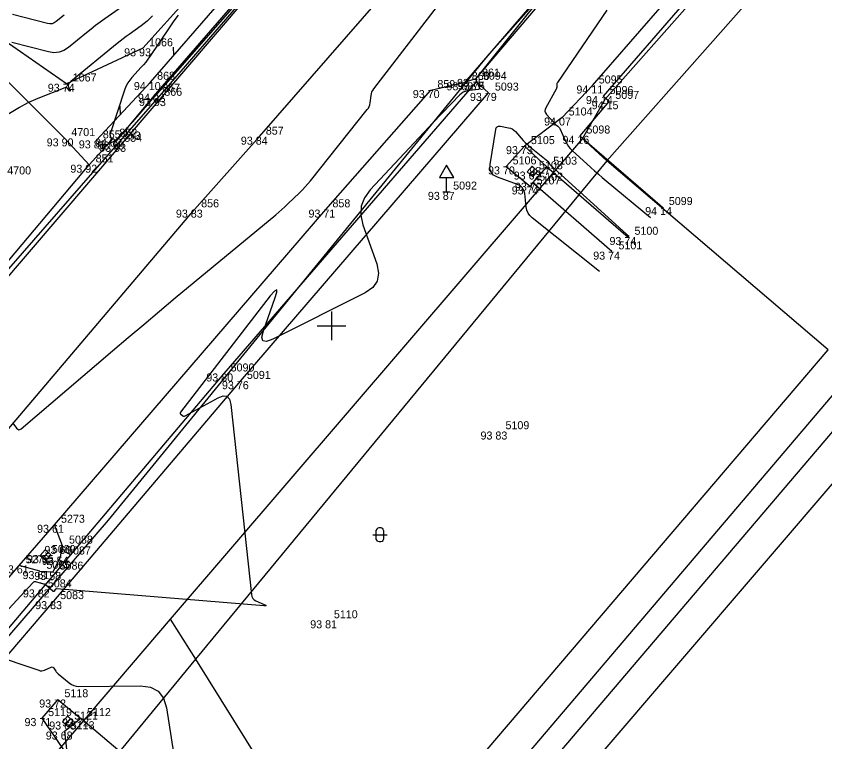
# Model space of a CAD drawing. Extents: x -711081 to -709338, y -1025122 to -1024092.
# Drawn here: x -709736.03 to -709707.76, y -1024464.55 to -1024439.18 of the extents above; entities that cross this region are included whole.
import ezdxf

# ---------------------------------------------------------------- set-up
doc = ezdxf.new("R2010")
doc.units = 0
for name, color, linetype in [('Ex_Major Contours', 7, 'Continuous'), ('Ex_Minor Contours', 7, 'Continuous'), ('Z_body', 7, 'Continuous'), ('Z_body_cisla', 7, 'Continuous'), ('Z_body_vysky_redukovane', 7, 'Continuous'), ('Z_dopravni_znacky', 7, 'Continuous'), ('Z_hektometricka_sit', 7, 'Continuous'), ('Z_hrany_paty', 7, 'Continuous'), ('Z_katastr_hranice', 7, 'Continuous'), ('Z_katastr_vnitrni_kresba', 7, 'Continuous'), ('Z_komunikace', 7, 'Continuous'), ('Z_obruba', 7, 'Continuous'), ('Z_rozhranni', 7, 'Continuous'), ('Z_site_kanalizace_znaky', 7, 'Continuous'), ('Z_svodidla', 7, 'Continuous'), ('Z_svodidla_znacky', 7, 'Continuous'), ('Z_svodidlo_betonove', 7, 'Continuous'), ('Z_vdz12_plna', 7, 'Continuous'), ('Z_vdz12_prerusovana', 7, 'Continuous'), ('Z_zlabek', 7, 'Continuous'), ('Z_znaky_kultur', 7, 'Continuous')]:
    doc.layers.add(name, color=color, linetype=linetype)

# ---------------------------------------------------------------- blocks, each defined once
blk = doc.blocks.new('POINT_DISPLAY')
blk.add_line((0, 0), (0, 0))
blk = doc.blocks.new('Z529')
blk.add_line((0, 0), (0.2, 0.2))
blk = doc.blocks.new('Z46260')
for p, q in [((0.13, 0.13), (-0.13, 0.13)), ((-0.13, 0.13), (-0.13, -0.13)), ((0.13, 0), (-0.13, 0)), ((0.13, -0.13), (0.13, 0.13)), ((-0.13, -0.13), (0.13, -0.13))]:
    blk.add_line(p, q)
blk = doc.blocks.new('Z527')
for p, q in [((0, 0.93), (-0.25, 0.5)), ((0.25, 0.5), (0, 0.93)), ((-0.25, 0.5), (0.25, 0.5)), ((0, 0), (0, 0.5)), ((-0.13, 0), (0.13, 0))]:
    blk.add_line(p, q)
blk = doc.blocks.new('Z316')
for p, q in [((-0.25, 0), (0.25, 0)), ((-0.13, 0.15), (-0.1, 0.2)), ((-0.13, -0.15), (-0.13, 0.15)), ((-0.1, 0.2), (-0.08, 0.23)), ((-0.08, 0.23), (-0.03, 0.25)), ((-0.03, 0.25), (0.03, 0.25)), ((0.03, 0.25), (0.08, 0.23)), ((0.08, 0.23), (0.1, 0.2)), ((0.1, 0.2), (0.13, 0.15)), ((0.13, 0.15), (0.13, -0.15)), ((-0.1, -0.2), (-0.13, -0.15)), ((-0.08, -0.23), (-0.1, -0.2)), ((-0.03, -0.25), (-0.08, -0.23)), ((0.03, -0.25), (-0.03, -0.25)), ((0.08, -0.23), (0.03, -0.25)), ((0.1, -0.2), (0.08, -0.23)), ((0.13, -0.15), (0.1, -0.2))]:
    blk.add_line(p, q)

msp = doc.modelspace()

# ---------------------------------------------------------------- linework, layer by layer
at = {"layer": 'Ex_Major Contours'}
for points in [[(-709730.362, -1024439.145), (-709730.511, -1024439.344), (-709730.653, -1024439.548), (-709731.353, -1024440.585), (-709731.423, -1024440.684), (-709731.496, -1024440.78), (-709731.573, -1024440.873), (-709731.653, -1024440.964), (-709731.982, -1024441.319), (-709732.059, -1024441.411), (-709732.125, -1024441.51), (-709732.18, -1024441.615), (-709732.223, -1024441.726), (-709732.744, -1024443.286), (-709732.749, -1024443.304), (-709732.75, -1024443.323), (-709732.747, -1024443.341), (-709732.741, -1024443.359), (-709732.711, -1024443.43), (-709732.706, -1024443.448), (-709732.705, -1024443.465), (-709732.709, -1024443.482), (-709732.717, -1024443.498), (-709732.78, -1024443.598), (-709732.789, -1024443.616), (-709732.789, -1024443.625), (-709732.78, -1024443.627), (-709732.761, -1024443.619), (-709732.627, -1024443.556), (-709732.598, -1024443.54), (-709732.57, -1024443.522), (-709732.544, -1024443.501), (-709732.52, -1024443.478), (-709732.192, -1024443.134), (-709732.13, -1024443.068), (-709732.068, -1024443.002), (-709732.008, -1024442.935), (-709731.948, -1024442.867), (-709731.362, -1024442.193), (-709731.244, -1024442.058), (-709731.126, -1024441.924), (-709731.009, -1024441.789), (-709730.891, -1024441.654), (-709726.88, -1024437.076)], [(-709715.38, -1024438.972), (-709717.104, -1024441.497), (-709717.114, -1024441.514), (-709717.121, -1024441.531), (-709717.125, -1024441.55), (-709717.127, -1024441.57), (-709717.128, -1024441.649), (-709717.129, -1024441.669), (-709717.133, -1024441.688), (-709717.139, -1024441.706), (-709717.147, -1024441.724), (-709717.514, -1024442.382), (-709717.538, -1024442.443), (-709717.542, -1024442.501), (-709717.526, -1024442.557), (-709717.489, -1024442.61), (-709717.245, -1024442.887), (-709717.227, -1024442.906), (-709717.208, -1024442.924), (-709717.189, -1024442.942), (-709717.169, -1024442.959), (-709717.086, -1024443.024), (-709717.067, -1024443.041), (-709717.05, -1024443.06), (-709717.035, -1024443.081), (-709717.023, -1024443.104), (-709716.811, -1024443.575), (-709716.768, -1024443.658), (-709716.717, -1024443.736), (-709716.658, -1024443.809), (-709716.592, -1024443.875), (-709715.94, -1024444.468), (-709715.808, -1024444.588), (-709715.673, -1024444.705), (-709715.538, -1024444.821), (-709715.401, -1024444.936), (-709713.85, -1024446.218)]]:
    msp.add_lwpolyline(points, dxfattribs=at)
at = {"layer": 'Ex_Minor Contours'}
for points in [[(-709731.728, -1024438.421), (-709732.924, -1024439.265), (-709733.089, -1024439.384), (-709733.251, -1024439.505), (-709733.411, -1024439.63), (-709733.569, -1024439.757), (-709734.196, -1024440.273), (-709734.358, -1024440.379), (-709734.53, -1024440.441), (-709734.711, -1024440.457), (-709734.903, -1024440.428), (-709736.179, -1024440.095)], [(-709717.931, -1024438.822), (-709718.222, -1024439.185), (-709719.944, -1024441.35), (-709719.95, -1024441.36), (-709719.954, -1024441.371), (-709719.955, -1024441.383), (-709719.953, -1024441.395), (-709719.938, -1024441.445), (-709719.934, -1024441.457), (-709719.929, -1024441.47), (-709719.924, -1024441.482), (-709719.919, -1024441.494), (-709719.839, -1024441.662), (-709719.83, -1024441.69), (-709719.833, -1024441.712), (-709719.849, -1024441.727), (-709719.878, -1024441.736), (-709720.258, -1024441.793), (-709720.33, -1024441.81), (-709720.397, -1024441.837), (-709720.458, -1024441.875), (-709720.513, -1024441.924), (-709721.128, -1024442.559), (-709721.248, -1024442.683), (-709721.367, -1024442.808), (-709721.486, -1024442.934), (-709721.604, -1024443.059), (-709723.649, -1024445.254), (-709723.851, -1024445.529), (-709723.961, -1024445.823), (-709723.978, -1024446.137), (-709723.904, -1024446.47), (-709723.421, -1024447.841), (-709723.356, -1024448.162), (-709723.403, -1024448.437), (-709723.56, -1024448.667), (-709723.829, -1024448.853), (-709727.049, -1024450.471), (-709727.271, -1024450.554), (-709727.4, -1024450.532), (-709727.437, -1024450.406), (-709727.382, -1024450.177), (-709726.979, -1024449.05), (-709726.914, -1024448.833), (-709726.92, -1024448.746), (-709726.996, -1024448.788), (-709727.144, -1024448.96), (-709730.284, -1024453.025), (-709730.295, -1024453.043), (-709730.297, -1024453.06), (-709730.291, -1024453.076), (-709730.276, -1024453.091), (-709730.202, -1024453.149), (-709730.183, -1024453.16), (-709730.164, -1024453.165), (-709730.144, -1024453.163), (-709730.124, -1024453.155), (-709728.968, -1024452.519), (-709728.791, -1024452.452), (-709728.657, -1024452.468), (-709728.567, -1024452.568), (-709728.521, -1024452.753), (-709727.805, -1024459.402), (-709727.789, -1024459.474), (-709727.757, -1024459.534), (-709727.709, -1024459.583), (-709727.645, -1024459.62), (-709727.359, -1024459.744), (-709727.306, -1024459.771), (-709727.29, -1024459.788), (-709727.312, -1024459.796), (-709727.371, -1024459.794), (-709734.615, -1024459.205), (-709734.63, -1024459.205), (-709734.643, -1024459.209), (-709734.655, -1024459.217), (-709734.665, -1024459.228), (-709734.701, -1024459.278), (-709734.711, -1024459.288), (-709734.721, -1024459.292), (-709734.732, -1024459.291), (-709734.743, -1024459.283), (-709734.997, -1024459.065), (-709735.01, -1024459.054), (-709735.025, -1024459.046), (-709735.041, -1024459.039), (-709735.057, -1024459.033), (-709735.126, -1024459.016), (-709735.143, -1024459.011), (-709735.16, -1024459.007), (-709735.177, -1024459.002), (-709735.194, -1024458.997), (-709735.34, -1024458.957), (-709735.369, -1024458.952), (-709735.396, -1024458.956), (-709735.42, -1024458.967), (-709735.442, -1024458.986), (-709737.12, -1024460.795)], [(-709736.15, -1024453.402), (-709736.011, -1024453.587), (-709735.975, -1024453.622), (-709735.937, -1024453.637), (-709735.896, -1024453.631), (-709735.853, -1024453.604), (-709732.664, -1024450.88), (-709732.117, -1024450.415), (-709731.568, -1024449.952), (-709731.018, -1024449.49), (-709730.465, -1024449.031), (-709726.948, -1024446.12), (-709726.84, -1024446.029), (-709726.734, -1024445.936), (-709726.629, -1024445.841), (-709726.526, -1024445.744), (-709726.118, -1024445.352), (-709726.018, -1024445.252), (-709725.921, -1024445.149), (-709725.827, -1024445.043), (-709725.737, -1024444.934), (-709723.751, -1024442.445), (-709723.714, -1024442.392), (-709723.686, -1024442.335), (-709723.666, -1024442.275), (-709723.653, -1024442.212), (-709723.622, -1024441.951), (-709723.61, -1024441.888), (-709723.59, -1024441.827), (-709723.562, -1024441.771), (-709723.526, -1024441.717), (-709721.294, -1024438.828)], [(-709731.267, -1024439.168), (-709731.356, -1024439.263), (-709731.451, -1024439.352), (-709731.55, -1024439.435), (-709731.654, -1024439.513), (-709732.08, -1024439.814), (-709732.186, -1024439.891), (-709732.29, -1024439.969), (-709732.393, -1024440.049), (-709732.495, -1024440.131), (-709734.113, -1024441.461), (-709734.121, -1024441.468), (-709734.129, -1024441.475), (-709734.137, -1024441.483), (-709734.144, -1024441.491), (-709734.176, -1024441.525), (-709734.182, -1024441.532), (-709734.187, -1024441.539), (-709734.191, -1024441.547), (-709734.194, -1024441.556), (-709734.206, -1024441.591), (-709734.208, -1024441.6), (-709734.209, -1024441.608), (-709734.207, -1024441.617), (-709734.205, -1024441.626), (-709734.143, -1024441.771), (-709734.136, -1024441.791), (-709734.136, -1024441.8), (-709734.144, -1024441.797), (-709734.16, -1024441.782), (-709734.236, -1024441.7), (-709734.256, -1024441.684), (-709734.277, -1024441.675), (-709734.301, -1024441.673), (-709734.326, -1024441.68), (-709735.27, -1024442.051), (-709735.434, -1024442.12), (-709735.595, -1024442.195), (-709735.753, -1024442.277), (-709735.907, -1024442.366), (-709736.677, -1024442.828)], [(-709734.354, -1024439.145), (-709734.625, -1024439.368), (-709734.694, -1024439.414), (-709734.769, -1024439.44), (-709734.847, -1024439.447), (-709734.93, -1024439.435), (-709736.156, -1024439.115)], [(-709715.638, -1024448.109), (-709717.987, -1024446.23), (-709718.069, -1024446.15), (-709718.132, -1024446.06), (-709718.174, -1024445.96), (-709718.197, -1024445.848), (-709718.249, -1024445.379), (-709718.275, -1024445.271), (-709718.324, -1024445.183), (-709718.398, -1024445.114), (-709718.497, -1024445.064), (-709719.203, -1024444.805), (-709719.335, -1024444.735), (-709719.421, -1024444.639), (-709719.463, -1024444.516), (-709719.459, -1024444.367), (-709719.262, -1024443.145), (-709719.243, -1024443.084), (-709719.209, -1024443.044), (-709719.16, -1024443.025), (-709719.097, -1024443.027), (-709718.812, -1024443.076), (-709718.744, -1024443.093), (-709718.682, -1024443.121), (-709718.625, -1024443.159), (-709718.574, -1024443.208), (-709718.297, -1024443.521), (-709718.234, -1024443.59), (-709718.167, -1024443.655), (-709718.098, -1024443.718), (-709718.026, -1024443.778), (-709717.441, -1024444.242), (-709717.431, -1024444.25), (-709717.422, -1024444.26), (-709717.415, -1024444.27), (-709717.409, -1024444.282), (-709717.388, -1024444.329), (-709717.382, -1024444.341), (-709717.375, -1024444.352), (-709717.367, -1024444.362), (-709717.358, -1024444.371), (-709714.687, -1024446.8), (-709714.679, -1024446.808), (-709714.67, -1024446.816), (-709714.661, -1024446.823), (-709714.653, -1024446.83), (-709714.6, -1024446.874)], [(-709736.95, -1024461.468), (-709735.235, -1024462.049), (-709735.184, -1024462.062), (-709735.134, -1024462.065), (-709735.085, -1024462.058), (-709735.035, -1024462.041), (-709734.799, -1024461.94), (-709734.772, -1024461.932), (-709734.747, -1024461.935), (-709734.726, -1024461.947), (-709734.708, -1024461.969), (-709734.641, -1024462.078), (-709734.624, -1024462.104), (-709734.604, -1024462.128), (-709734.583, -1024462.151), (-709734.559, -1024462.172), (-709734.172, -1024462.492), (-709734.096, -1024462.544), (-709734.016, -1024462.581), (-709733.929, -1024462.603), (-709733.838, -1024462.61), (-709731.677, -1024462.593), (-709731.326, -1024462.639), (-709731.059, -1024462.782), (-709730.874, -1024463.022), (-709730.772, -1024463.361), (-709730.279, -1024466.513)]]:
    msp.add_lwpolyline(points, dxfattribs=at)
at = {"layer": 'Z_hektometricka_sit'}
for p, q in [((-709725, -1024449.5), (-709725, -1024450.5)), ((-709725.5, -1024450), (-709724.5, -1024450))]:
    msp.add_line(p, q, dxfattribs=at)
at = {"layer": 'Z_hrany_paty'}
for p, q in [((-709726.88, -1024435.04), (-709731.6, -1024440.3)), ((-709734.27, -1024441.54), (-709737.37, -1024439.39)), ((-709731.6, -1024440.3), (-709734.27, -1024441.54))]:
    msp.add_line(p, q, dxfattribs=at)
at = {"layer": 'Z_katastr_hranice'}
for p, q in [((-709705.62, -1024430.99), (-709715.45, -1024442.09)), ((-709715.45, -1024442.09), (-709716.23, -1024443.45)), ((-709716.23, -1024443.45), (-709730.64, -1024460.26)), ((-709715.38, -1024444.24), (-709716.23, -1024443.45)), ((-709707.64, -1024450.84), (-709715.38, -1024444.24)), ((-709730.64, -1024460.26), (-709735.48, -1024465.91)), ((-709730.64, -1024460.26), (-709729.76, -1024461.66)), ((-709729.76, -1024461.66), (-709724.31, -1024470.38))]:
    msp.add_line(p, q, dxfattribs=at)
at = {"layer": 'Z_katastr_vnitrni_kresba'}
for p, q in [((-709719.49, -1024440.51), (-709707.87, -1024427.32)), ((-709715.38, -1024444.24), (-709704.82, -1024432.3)), ((-709725.38, -1024435.5), (-709769.86, -1024487.47)), ((-709732.8, -1024456.8), (-709719.49, -1024440.51)), ((-709715.38, -1024444.24), (-709729.76, -1024461.66)), ((-709724.31, -1024470.38), (-709707.64, -1024450.84)), ((-709723.64, -1024471.44), (-709706.77, -1024451.59)), ((-709706.15, -1024452.12), (-709723.19, -1024472.15)), ((-709705.25, -1024452.89), (-709722.57, -1024473.13)), ((-709754.46, -1024481.94), (-709732.8, -1024456.8)), ((-709729.76, -1024461.66), (-709734.52, -1024467.43))]:
    msp.add_line(p, q, dxfattribs=at)
at = {"layer": 'Z_komunikace'}
for p, q in [((-709731.08, -1024442.04), (-709719.72, -1024428.91)), ((-709720.33, -1024441.49), (-709713.34, -1024433.37)), ((-709710.24, -1024435.89), (-709715.5, -1024441.97)), ((-709734.33, -1024443.45), (-709737.89, -1024439.9)), ((-709721.53, -1024441.76), (-709720.33, -1024441.49)), ((-709725.2, -1024445.94), (-709721.53, -1024441.76)), ((-709715.5, -1024441.97), (-709715.3, -1024442.15)), ((-709732.47, -1024443.64), (-709731.08, -1024442.04)), ((-709715.3, -1024442.15), (-709716.32, -1024443.36)), ((-709716.32, -1024443.36), (-709713.43, -1024445.85)), ((-709737.55, -1024449.46), (-709732.47, -1024443.64)), ((-709734.33, -1024443.45), (-709733.48, -1024444.37)), ((-709734.69, -1024456.96), (-709725.2, -1024445.94)), ((-709735.92, -1024458.38), (-709734.69, -1024456.96)), ((-709734.41, -1024457.7), (-709734.69, -1024456.96)), ((-709734.48, -1024458.08), (-709734.41, -1024457.7)), ((-709734.74, -1024458.61), (-709734.48, -1024458.08)), ((-709740.66, -1024463.89), (-709735.92, -1024458.38)), ((-709735.2, -1024458.58), (-709735.92, -1024458.38)), ((-709735.2, -1024458.58), (-709734.74, -1024458.61))]:
    msp.add_line(p, q, dxfattribs=at)
at = {"layer": 'Z_obruba'}
for p, q in [((-709731.14, -1024441.89), (-709719.85, -1024428.88)), ((-709719.96, -1024441.37), (-709713.42, -1024433.69)), ((-709719.96, -1024441.37), (-709720.33, -1024441.49)), ((-709732.53, -1024443.56), (-709731.14, -1024441.89)), ((-709733.48, -1024444.37), (-709732.64, -1024443.46)), ((-709732.64, -1024443.46), (-709732.53, -1024443.56)), ((-709737.58, -1024449.25), (-709733.48, -1024444.37))]:
    msp.add_line(p, q, dxfattribs=at)
at = {"layer": 'Z_rozhranni'}
for p, q in [((-709715.88, -1024441.6), (-709710.61, -1024435.54)), ((-709715.88, -1024441.6), (-709716.94, -1024442.72)), ((-709716.94, -1024442.72), (-709718.25, -1024443.72)), ((-709718.25, -1024443.72), (-709718.9, -1024444.43)), ((-709718.25, -1024443.72), (-709717.48, -1024444.45)), ((-709718.9, -1024444.43), (-709718.05, -1024445.13)), ((-709718.05, -1024445.13), (-709717.96, -1024445)), ((-709734.57, -1024463.07), (-709735.13, -1024463.72)), ((-709734.57, -1024463.07), (-709733.77, -1024463.73)), ((-709735.13, -1024463.72), (-709734.25, -1024465.02))]:
    msp.add_line(p, q, dxfattribs=at)
at = {"layer": 'Z_svodidla'}
for p, q in [((-709731.33, -1024441.48), (-709720.14, -1024428.59)), ((-709733.23, -1024443.52), (-709731.33, -1024441.48))]:
    msp.add_line(p, q, dxfattribs=at)
at = {"layer": 'Z_svodidlo_betonove'}
for p, q in [((-709728.75, -1024451.67), (-709719.93, -1024441.47)), ((-709719.51, -1024441.86), (-709719.93, -1024441.47)), ((-709728.18, -1024451.94), (-709719.51, -1024441.86)), ((-709735.14, -1024459.22), (-709728.75, -1024451.67)), ((-709734.71, -1024459.63), (-709728.18, -1024451.94)), ((-709746.27, -1024472.32), (-709735.14, -1024459.22)), ((-709745.9, -1024472.72), (-709734.71, -1024459.63))]:
    msp.add_line(p, q, dxfattribs=at)
at = {"layer": 'Z_vdz12_plna'}
msp.add_line((-709743.08, -1024461.6), (-709729.79, -1024445.94), dxfattribs=at)
at = {"layer": 'Z_vdz12_prerusovana'}
for q in [(-709716.33, -1024430.53), (-709729.79, -1024445.94)]:
    msp.add_line((-709727.52, -1024443.39), q, dxfattribs=at)
at = {"layer": 'Z_zlabek'}
for p, q in [((-709717.96, -1024445), (-709717.48, -1024444.45)), ((-709717.48, -1024444.45), (-709714.63, -1024446.9)), ((-709715.2, -1024447.41), (-709717.96, -1024445)), ((-709733.77, -1024463.73), (-709734.34, -1024464.19)), ((-709730.25, -1024466.7), (-709733.77, -1024463.73)), ((-709734.34, -1024464.19), (-709734.25, -1024465.02))]:
    msp.add_line(p, q, dxfattribs=at)

# ---------------------------------------------------------------- block references
at = {"layer": 'Z_body'}
for p in [(-709731.6, -1024440.3), (-709719.96, -1024441.37), (-709734.27, -1024441.54), (-709731.33, -1024441.48), (-709720.33, -1024441.49), (-709719.93, -1024441.47), (-709715.88, -1024441.6), (-709731.14, -1024441.89), (-709721.53, -1024441.76), (-709719.51, -1024441.86), (-709715.5, -1024441.97), (-709731.08, -1024442.04), (-709715.3, -1024442.15), (-709716.94, -1024442.72), (-709727.52, -1024443.39), (-709716.32, -1024443.36), (-709734.33, -1024443.45), (-709733.23, -1024443.52), (-709732.64, -1024443.46), (-709732.53, -1024443.56), (-709732.47, -1024443.64), (-709718.25, -1024443.72), (-709733.48, -1024444.37), (-709718.9, -1024444.43), (-709717.48, -1024444.45), (-709717.98, -1024444.61), (-709717.96, -1024445), (-709720.98, -1024445.32), (-709718.05, -1024445.13), (-709729.79, -1024445.94), (-709725.2, -1024445.94), (-709713.43, -1024445.85), (-709714.63, -1024446.9), (-709715.2, -1024447.41), (-709728.75, -1024451.67), (-709728.18, -1024451.94), (-709719.14, -1024453.7), (-709734.69, -1024456.96), (-709734.41, -1024457.7), (-709735, -1024458.02), (-709734.48, -1024458.08), (-709735.92, -1024458.38), (-709735.2, -1024458.58), (-709734.74, -1024458.61), (-709735.14, -1024459.22), (-709734.71, -1024459.63), (-709725.14, -1024460.3), (-709734.57, -1024463.07), (-709735.13, -1024463.72), (-709733.77, -1024463.73), (-709734.22, -1024463.84), (-709734.34, -1024464.19)]:
    msp.add_blockref('POINT_DISPLAY', p, dxfattribs=at)
at = {"layer": 'Z_dopravni_znacky'}
msp.add_blockref('Z527', (-709720.98, -1024445.32), dxfattribs=at)
at = {"layer": 'Z_site_kanalizace_znaky'}
for p, rotation in [((-709717.98, -1024444.61), 48.6), ((-709735, -1024458.02), 48.6), ((-709734.22, -1024463.84), 49.500000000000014)]:
    msp.add_blockref('Z46260', p, dxfattribs=dict(at, rotation=rotation))
at = {"layer": 'Z_svodidla_znacky'}
for p, rotation in [((-709730.51, -1024440.54), 48.99999999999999), ((-709732.38, -1024442.61), 47)]:
    msp.add_blockref('Z529', p, dxfattribs=dict(at, rotation=rotation))
at = {"layer": 'Z_znaky_kultur'}
msp.add_blockref('Z316', (-709723.31, -1024457.31), dxfattribs=at)

# ---------------------------------------------------------------- texts
at = {"layer": 'Z_body_cisla'}
for s, p in [('1066', (-709731.38, -1024440.23)), ('868', (-709731.1, -1024441.4)), ('860', (-709720.1, -1024441.41)), ('861', (-709719.74, -1024441.29)), ('5094', (-709719.71, -1024441.4)), ('1067', (-709734.05, -1024441.46)), ('859', (-709721.3, -1024441.69)), ('5095', (-709715.66, -1024441.53)), ('867', (-709730.92, -1024441.82)), ('866', (-709730.85, -1024441.96)), ('5093', (-709719.29, -1024441.78)), ('5096', (-709715.28, -1024441.9)), ('5097', (-709715.08, -1024442.07)), ('5104', (-709716.71, -1024442.65)), ('4701', (-709734.1, -1024443.37)), ('852', (-709732.42, -1024443.39)), ('857', (-709727.3, -1024443.32)), ('5098', (-709716.09, -1024443.28)), ('855', (-709733, -1024443.45)), ('853', (-709732.3, -1024443.49)), ('854', (-709732.25, -1024443.57)), ('5105', (-709718.03, -1024443.65)), ('851', (-709733.25, -1024444.29)), ('5106', (-709718.67, -1024444.36)), ('5108', (-709717.75, -1024444.53)), ('5103', (-709717.25, -1024444.37)), ('4700', (-709736.34, -1024444.71)), ('5107', (-709717.83, -1024445.06)), ('5102', (-709717.74, -1024444.93)), ('5092', (-709720.75, -1024445.24)), ('856', (-709729.56, -1024445.86)), ('858', (-709724.97, -1024445.86)), ('5099', (-709713.21, -1024445.78)), ('5100', (-709714.41, -1024446.82)), ('5101', (-709714.97, -1024447.33)), ('5090', (-709728.53, -1024451.6)), ('5091', (-709727.96, -1024451.86)), ('5109', (-709718.92, -1024453.62)), ('5273', (-709734.46, -1024456.89)), ('5088', (-709734.18, -1024457.62)), ('5089', (-709734.78, -1024457.95)), ('5087', (-709734.25, -1024458)), ('5272', (-709735.7, -1024458.31)), ('5085', (-709734.97, -1024458.5)), ('5086', (-709734.51, -1024458.53)), ('5084', (-709734.92, -1024459.15)), ('5083', (-709734.49, -1024459.56)), ('5110', (-709724.92, -1024460.23)), ('5118', (-709734.34, -1024462.99)), ('5119', (-709734.91, -1024463.65)), ('5121', (-709734, -1024463.77)), ('5112', (-709733.55, -1024463.65)), ('5113', (-709734.12, -1024464.11))]:
    msp.add_text(s, height=0.28, dxfattribs=at).set_placement(p)
at = {"layer": 'Z_body_vysky_redukovane'}
for s, p in [('93 93', (-709732.253, -1024440.58)), ('93 75', (-709720.613, -1024441.65)), ('93 74', (-709734.923, -1024441.82)), ('94 10', (-709731.913, -1024441.76)), ('93 68', (-709720.983, -1024441.77)), ('93 75', (-709720.583, -1024441.75)), ('94 11', (-709716.44, -1024441.88)), ('94 02', (-709731.77, -1024442.17)), ('93 70', (-709722.16, -1024442.04)), ('93 79', (-709720.163, -1024442.14)), ('94 14', (-709716.107, -1024442.25)), ('93 93', (-709731.733, -1024442.32)), ('94 15', (-709715.907, -1024442.43)), ('94 07', (-709717.57, -1024443)), ('93 84', (-709728.173, -1024443.67)), ('94 16', (-709716.927, -1024443.64)), ('93 90', (-709734.96, -1024443.73)), ('93 81', (-709733.837, -1024443.8)), ('94 02', (-709733.27, -1024443.74)), ('93 99', (-709733.183, -1024443.84)), ('93 93', (-709733.123, -1024443.92)), ('93 73', (-709718.903, -1024444)), ('93 92', (-709734.133, -1024444.65)), ('93 70', (-709719.53, -1024444.71)), ('93 71', (-709718.087, -1024444.73)), ('93 62', (-709718.633, -1024444.89)), ('93 70', (-709718.59, -1024445.28)), ('93 87', (-709721.633, -1024445.6)), ('93 74', (-709718.703, -1024445.41)), ('93 83', (-709730.443, -1024446.22)), ('93 71', (-709725.807, -1024446.22)), ('94 14', (-709714.037, -1024446.13)), ('93 74', (-709715.283, -1024447.18)), ('93 74', (-709715.853, -1024447.69)), ('93 80', (-709729.38, -1024451.95)), ('93 76', (-709728.833, -1024452.22)), ('93 83', (-709719.793, -1024453.98)), ('93 61', (-709735.297, -1024457.24)), ('93 60', (-709735.04, -1024457.98)), ('93 55', (-709735.653, -1024458.3)), ('93 54', (-709735.133, -1024458.36)), ('93 61', (-709736.527, -1024458.66)), ('93 61', (-709735.807, -1024458.86)), ('93 58', (-709735.393, -1024458.89)), ('93 82', (-709735.793, -1024459.5)), ('93 83', (-709735.363, -1024459.91)), ('93 81', (-709725.747, -1024460.58)), ('93 72', (-709735.223, -1024463.35)), ('93 71', (-709735.737, -1024464)), ('93 72', (-709734.423, -1024464.01)), ('93 63', (-709734.873, -1024464.12)), ('93 68', (-709734.993, -1024464.47))]:
    msp.add_text(s, height=0.28, dxfattribs=at).set_placement(p)

doc.saveas('drawing.dxf')
